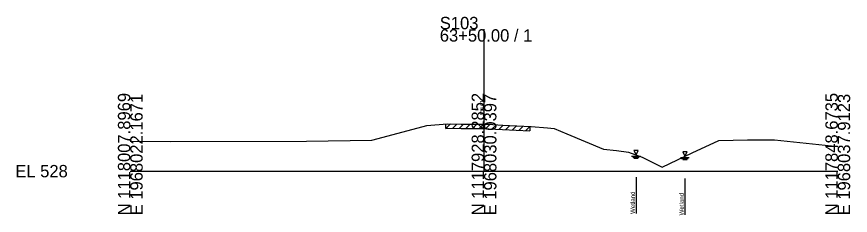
# Model space of a CAD drawing. Extents: x -26 to 163, y -10 to 45020.
# Drawn here: x -25.7 to 162.8, y 22490 to 22534.9 of the extents above; entities that cross this region are included whole.
import ezdxf

# ---------------------------------------------------------------- set-up
doc = ezdxf.new("R2010")
doc.units = 0
for name, color, linetype in [('RD_GPK_XS_Cell', 7, 'Continuous'), ('RD_XS_ExGround', 7, 'Continuous'), ('RD_XS_ExPaveRet', 7, 'Continuous'), ('RD_XS_EXWetland', 7, 'Continuous'), ('RD_XS_TX_Elev_EX', 7, 'Continuous')]:
    doc.layers.add(name, color=color, linetype=linetype)

msp = doc.modelspace()

# ---------------------------------------------------------------- linework, layer by layer
at = {"layer": 'RD_GPK_XS_Cell'}
for p, q in [((80, 22500), (80, 22532.09)), ((0, 22500), (80, 22500)), ((80, 22500), (160, 22500))]:
    msp.add_line(p, q, dxfattribs=at)
at = {"layer": 'RD_XS_ExGround'}
for p, q in [((59.47, 22508.26), (67.08, 22510.3)), ((67.08, 22510.3), (68.91, 22510.44)), ((68.91, 22510.44), (71.77, 22510.7)), ((71.77, 22510.7), (74.8, 22510.64)), ((74.8, 22510.64), (80, 22510.61)), ((80, 22510.61), (80.9, 22510.6)), ((80.9, 22510.6), (84.21, 22510.4)), ((84.21, 22510.4), (90.69, 22510.08)), ((90.69, 22510.08), (94.33, 22509.77)), ((94.33, 22509.77), (95.85, 22509.66)), ((95.85, 22509.66), (98.75, 22508.41)), ((54.6, 22507), (59.47, 22508.26)), ((98.75, 22508.41), (107.04, 22504.99)), ((133.1, 22506.96), (139.62, 22507.1)), ((139.62, 22507.1), (145.7, 22507.06)), ((145.7, 22507.06), (160, 22505.6)), ((0, 22506.78), (9.07, 22506.7)), ((9.07, 22506.7), (39.87, 22506.77)), ((39.87, 22506.77), (54.6, 22507)), ((127.1, 22504.16), (133.1, 22506.96)), ((107.04, 22504.99), (109.97, 22504.64)), ((109.97, 22504.64), (112.64, 22504.32)), ((112.64, 22504.32), (115.73, 22503.17)), ((120.27, 22500.88), (127.1, 22504.16)), ((115.73, 22503.17), (120.27, 22500.88))]:
    msp.add_line(p, q, dxfattribs=at)
at = {"layer": 'RD_XS_ExPaveRet'}
for p, q in [((71.37, 22509.66), (72.4, 22510.68)), ((71.37, 22509.66), (71.37, 22510.66)), ((71.37, 22509.66), (71.77, 22509.7)), ((71.77, 22509.7), (74.8, 22509.64)), ((72.87, 22509.68), (73.85, 22510.66)), ((74.37, 22509.65), (75.36, 22510.64)), ((74.8, 22509.64), (80, 22509.61)), ((75.87, 22509.63), (76.87, 22510.63)), ((77.37, 22509.62), (78.37, 22510.62)), ((78.87, 22509.61), (79.87, 22510.61)), ((80, 22509.61), (80.9, 22509.6)), ((80.37, 22509.6), (81.34, 22510.57)), ((80.9, 22509.6), (84.21, 22509.4)), ((81.87, 22509.54), (82.82, 22510.49)), ((83.38, 22509.45), (84.32, 22510.4)), ((84.21, 22509.4), (90.34, 22509.09)), ((84.88, 22509.37), (85.83, 22510.32)), ((86.38, 22509.29), (87.33, 22510.25)), ((87.88, 22509.22), (88.83, 22510.17)), ((89.38, 22509.14), (90.33, 22510.09)), ((90.34, 22510.09), (90.34, 22509.09))]:
    msp.add_line(p, q, dxfattribs=at)
at = {"layer": 'RD_XS_EXWetland'}
for p, q in [((113.37, 22503.42), (115.37, 22503.42)), ((113.87, 22504.67), (114.37, 22503.67)), ((114.87, 22504.67), (113.87, 22504.67)), ((114.37, 22503.67), (114.87, 22504.67)), ((124.93, 22504.36), (125.43, 22503.36)), ((125.93, 22504.36), (124.93, 22504.36)), ((125.43, 22503.36), (125.93, 22504.36)), ((113.62, 22503.17), (115.12, 22503.17)), ((113.87, 22502.92), (114.87, 22502.92)), ((124.43, 22503.11), (126.43, 22503.11)), ((124.68, 22502.86), (126.18, 22502.86)), ((124.93, 22502.61), (125.93, 22502.61)), ((114.37, 22498.67), (114.37, 22490.42)), ((125.43, 22498.36), (125.43, 22490.11))]:
    msp.add_line(p, q, dxfattribs=at)

# ---------------------------------------------------------------- texts
at = {"layer": 'RD_GPK_XS_Cell'}
for s, p in [('S103', (70, 22532.09)), ('63+50.00 / 1', (70, 22529.29)), ('EL 528', (-26, 22498.6))]:
    msp.add_text(s, height=2.8, dxfattribs=at).set_placement(p)
for s, p in [('N 1118007.8969', (0, 22490)), ('E 1968022.1671', (2.8, 22490)), ('N 1117928.2852', (80, 22490)), ('E 1968030.0397', (82.8, 22490)), ('N 1117848.6735', (160, 22490)), ('E 1968037.9123', (162.8, 22490))]:
    msp.add_text(s, height=2.8, rotation=90, dxfattribs=at).set_placement(p)
at = {"layer": 'RD_XS_EXWetland'}
for p in [(114.12, 22490.32), (125.18, 22490)]:
    msp.add_text('Wetland ', height=1, rotation=90, dxfattribs=at).set_placement(p)
at = {"layer": 'RD_XS_TX_Elev_EX'}
msp.add_text('538.61', height=0.8, rotation=90, dxfattribs=at).set_placement((79.9, 22512.61))

doc.saveas('drawing.dxf')
